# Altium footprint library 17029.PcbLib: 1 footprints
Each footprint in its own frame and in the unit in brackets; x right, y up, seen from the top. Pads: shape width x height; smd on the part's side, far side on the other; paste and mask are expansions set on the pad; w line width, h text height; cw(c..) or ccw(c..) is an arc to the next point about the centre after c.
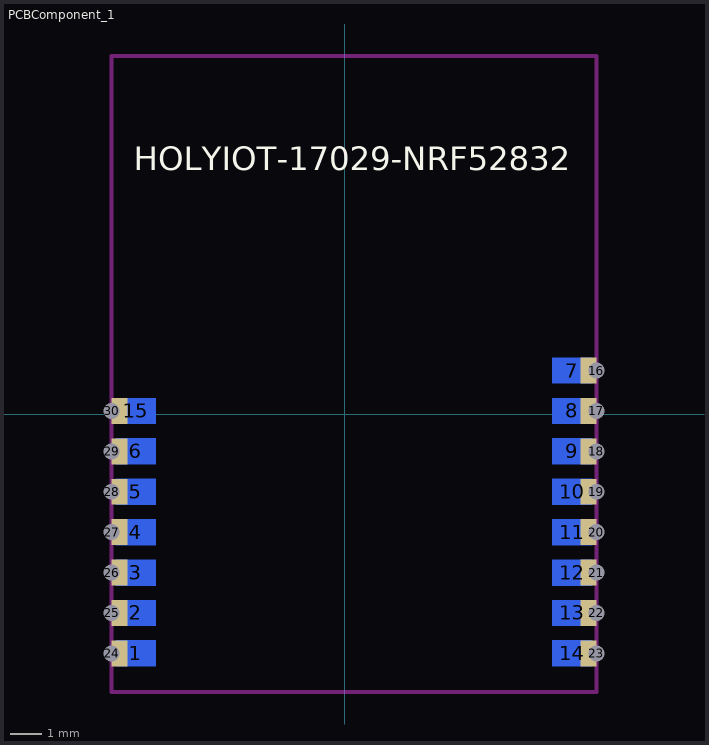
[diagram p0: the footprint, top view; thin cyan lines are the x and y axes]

## PCBComponent_1 [mil]
pads (30):
  rect 50x32 smd far side: 1(-258.46,-295.9) 2(-258.46,-245.9) 3(-258.46,-195.9) 4(-258.46,-145.9) 5(-258.46,-95.9) 6(-258.46,-45.9) 7(281.54,54.1) 8(281.54,4.1) 9(281.54,-45.9) 10(281.54,-95.9) 11(281.54,-145.9) 12(281.54,-195.9) 13(281.54,-245.9) 14(281.54,-295.9) 15(-258.46,4.1)
  rect 20x32 hole 19.68 copper offset -10,0: 16(311.54,54.1) 17(311.54,4.1) 18(311.54,-45.9) 19(311.54,-95.9) 20(311.54,-145.9) 21(311.54,-195.9) 22(311.54,-245.9) 23(311.54,-295.9)
  rect 20x32 hole 19.68 copper offset 10,0: 24(-288.46,-295.9) 25(-288.46,-245.9) 26(-288.46,-195.9) 27(-288.46,-145.9) 28(-288.46,-95.9) 29(-288.46,-45.9) 30(-288.46,4.1)
Top Overlay:
  text "HOLYIOT-17029-NRF52832" at -260.91,301.77 h29.53
Bottom Overlay:
  text "P0.28" at -110.12,-207.94 h23.62
  text "P0.29" at -110.12,-256.82 h23.62
  text "P0.30" at -110.12,-305.71 h23.62
  text "VDD" at -153.41,-61.29 h23.62
  text "GND" at -153.41,-12.4 h23.62
  text "P0.27" at -110.12,-159.06 h23.62
  text "P0.26" at -110.12,-110.17 h23.62
  text "P0.13" at 244.21,-207.85 h23.62
  text "P0.12" at 244.21,-257.56 h23.62
  text "P0.11" at 244.21,-307.28 h23.62
  text "P0.21" at 244.21,40.75 h23.62
  text "P0.18" at 244.21,-8.97 h23.62
  text "SWDIO" at 244.21,-158.13 h23.62
  text "SWDCLK" at 244.21,-108.41 h23.62
  text "P0.17" at 244.21,-58.69 h23.62
Keep-Out Layer:
  lines w5: -288.46,-343.9 -288.46,443.5 311.54,443.5 311.54,-343.9 -288.46,-343.9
